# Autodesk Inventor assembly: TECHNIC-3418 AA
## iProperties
Created: 2008-01
Part Number: TECHNIC-3418 AA
Document SubType Name: Assembly
Designer: eruiz-tagle
Mass: 48.6078 g
Surface Area: 636.847 cm^2
Volume: 39.7217 cm^3
Density: 1.22371 g/cm^3
Author: eruiz-tagle
